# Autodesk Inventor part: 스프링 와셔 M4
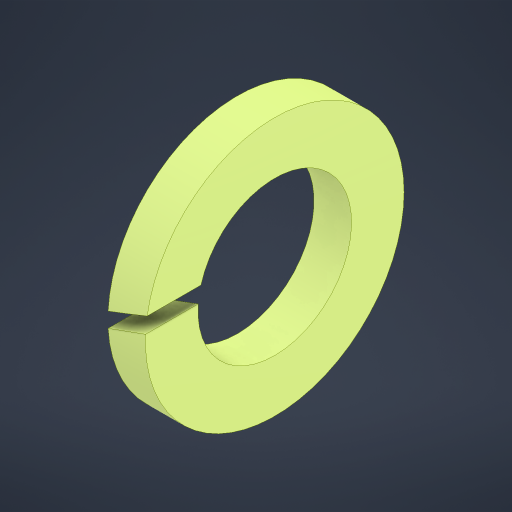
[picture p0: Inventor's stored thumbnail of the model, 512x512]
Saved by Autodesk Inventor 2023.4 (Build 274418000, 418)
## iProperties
Created: 2024-05
Part Number: 스프링 와셔 M4
Material: 강철, 연강
Description: 스프링 잠금 와셔
Document SubType Name: Modeling
Designer: Edu03
Density: 7.85 g/cm^3
Appearance: 기본값
Sending System: Autodesk Inventor 2025
Preprocessor: ST-DEVELOPER v20
Author: jhkim
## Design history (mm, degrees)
node "스프링 와셔 M41"
node "솔리드1"
body "Solid1"
